(* Logix 5000 project; controller Motion_Axis_AOIs_AMCI_RSLogix_V31 vendor 1 type 14 code 108 rev 31.11; software revision 31.02; part 2 of 7 *)
(* tags used below, declared in another part *)
   Initialize_timer : TIMER;
(* AMCI_MA_Reset_Driver_Fault, continued *)

ROUTINE Logic   (* ladder *)
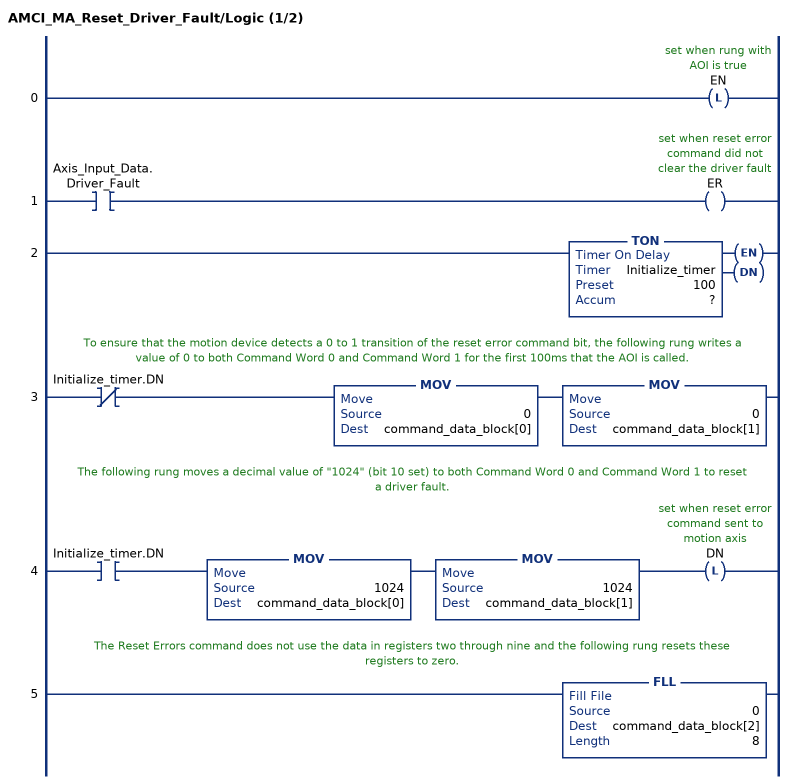
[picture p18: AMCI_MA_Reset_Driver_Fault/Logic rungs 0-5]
   0: OTL(EN);
   1: XIC(Axis_Input_Data.Driver_Fault)OTE(ER);
   2: TON(Initialize_timer,?,?);
   // To ensure that the motion device detects a 0 to 1 transition of the reset error command bit, the following rung writes a value of 0 to both Command Word 0 and Command Word 1 for the first 100ms that the AOI is called.
   3: XIO(Initialize_timer.DN)MOV(0,command_data_block[0])MOV(0,command_data_block[1]);
   // The following rung moves a decimal value of "1024" (bit 10 set) to both Command Word 0 and Command Word 1 to reset a driver fault.
   4: XIC(Initialize_timer.DN)MOV(1024,command_data_block[0])MOV(1024,command_data_block[1])OTL(DN);
   // The Reset Errors command does not use the data in registers two through nine and the following rung resets these registers to zero.
   5: FLL(0,command_data_block[2],8);
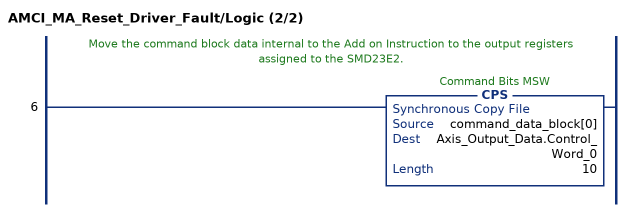
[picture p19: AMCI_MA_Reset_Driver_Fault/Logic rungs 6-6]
   // Move the command block data internal to the Add on Instruction to the output registers assigned to the SMD23E2.
   6: CPS(command_data_block[0],Axis_Output_Data.Control_Word_0,10);
END_ROUTINE
END_ADD_ON_INSTRUCTION

ADD_ON_INSTRUCTION AMCI_MA_Run_Blend_Move   (* revision 1.0, vendor AMCI, ExecuteEnableInFalse *)
// Run Blend Moves for SD and SMD devices.  Will not work with SV integrated servo devices.
// Help:
// MOTION AXIS RUN BLEND MOVE
// This AOI will only work with the SD and SMD motion devices.  The SV motion devices do not support Assembled Moves.
// AXIS INPUT DATA:  Input data from AMCI motion device.   Uses the AMCI_Motion_Axis_Input_Data User Defined Data Type.
// AXIS OUTPUT DATA; Output data from the AOI to the AMCI motion device.   Uses the AMCI_Motion_Axis_Output_Data User Defined Data Type.
// DIRECTION: 0 = CW motion 1 = CCW motion
// EN (Enable) Set when rung is true, Reset when rung is false
// DN (Done) Set when command is sent to the motion device.  Reset when the rung is false.
// ER (Error) Set when a command or input error failed to clear.  Reset when the rung is false.
// IP (In Process) Set when motion is occurring.   Reset when motion stops or the rung goes false.
VAR_IN_OUT
   Axis_Input_Data : AMCI_Motion_Axis_Input_Data; {required}
   Axis_Output_Data : AMCI_Motion_Axis_Output_Data; {required}
END_VAR
VAR_INPUT
   Type_0_for_standard_1_for_indexed : BOOL;
   Direction_0_for_CW_1_for_CCW : BOOL; {required}
END_VAR
VAR_OUTPUT
   EN : BOOL; {access Read Only, visible}
   DN : BOOL; {access Read Only, visible}
   ER : BOOL; {access Read Only, visible}
   IP : BOOL; {access Read Only, visible}
END_VAR
VAR
   command_data_block : INT[10];
        [1]   // Command Bits LSW
        [2]   // Upper Target Position
        [5]   // Lower Programmed Speed
        [0]   // Command Bits MSW
        [4]   // Upper Programmed Speed
        [3]   // Lower Target Position
END_VAR

ROUTINE EnableInFalse   (* ladder *)
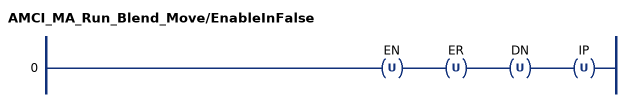
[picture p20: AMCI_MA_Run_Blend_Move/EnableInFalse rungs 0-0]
   0: OTU(EN)OTU(ER)OTU(DN)OTU(IP);
END_ROUTINE

ROUTINE Logic   (* ladder *)
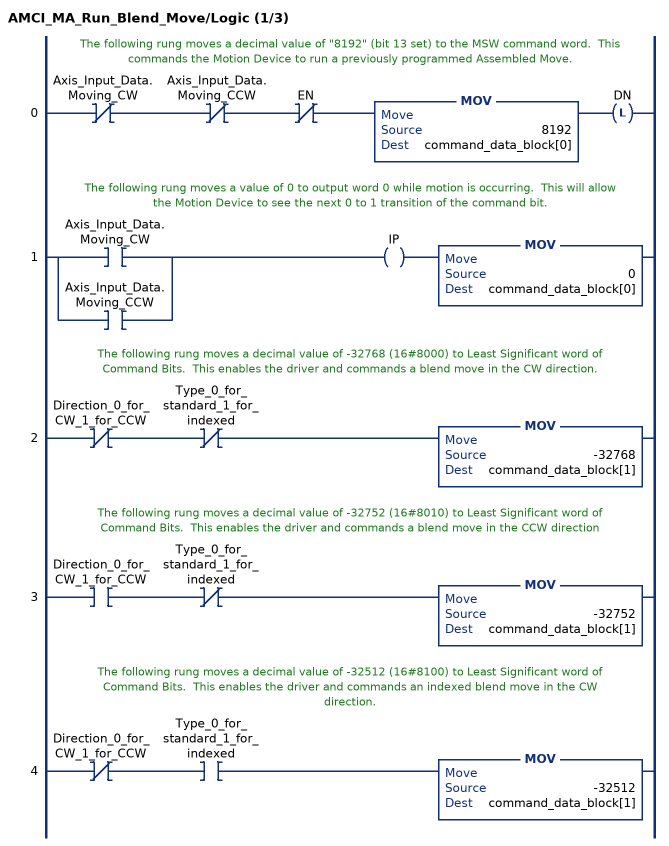
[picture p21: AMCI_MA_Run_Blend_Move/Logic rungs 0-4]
   // The following rung moves a decimal value of "8192" (bit 13 set) to the MSW command word.  This commands the Motion Device to run a previously programmed Assembled Move.
   0: XIO(Axis_Input_Data.Moving_CW)XIO(Axis_Input_Data.Moving_CCW)XIO(EN)MOV(8192,command_data_block[0])OTL(DN);
   // The following rung moves a value of 0 to output word 0 while motion is occurring.  This will allow the Motion Device to see the next 0 to 1 transition of the command bit.
   1: [XIC(Axis_Input_Data.Moving_CW) ,XIC(Axis_Input_Data.Moving_CCW) ]OTE(IP)MOV(0,command_data_block[0]);
   // The following rung moves a decimal value of -32768 (16#8000) to Least Significant word of Command Bits.  This enables the driver and commands a blend move in the CW direction.
   2: XIO(Direction_0_for_CW_1_for_CCW)XIO(Type_0_for_standard_1_for_indexed)MOV(-32768,command_data_block[1]);
   // The following rung moves a decimal value of -32752 (16#8010) to Least Significant word of Command Bits.  This enables the driver and commands a blend move in the CCW direction
   3: XIC(Direction_0_for_CW_1_for_CCW)XIO(Type_0_for_standard_1_for_indexed)MOV(-32752,command_data_block[1]);
   // The following rung moves a decimal value of -32512 (16#8100) to Least Significant word of Command Bits.  This enables the driver and commands an indexed blend move in the CW direction.
   4: XIO(Direction_0_for_CW_1_for_CCW)XIC(Type_0_for_standard_1_for_indexed)MOV(-32512,command_data_block[1]);
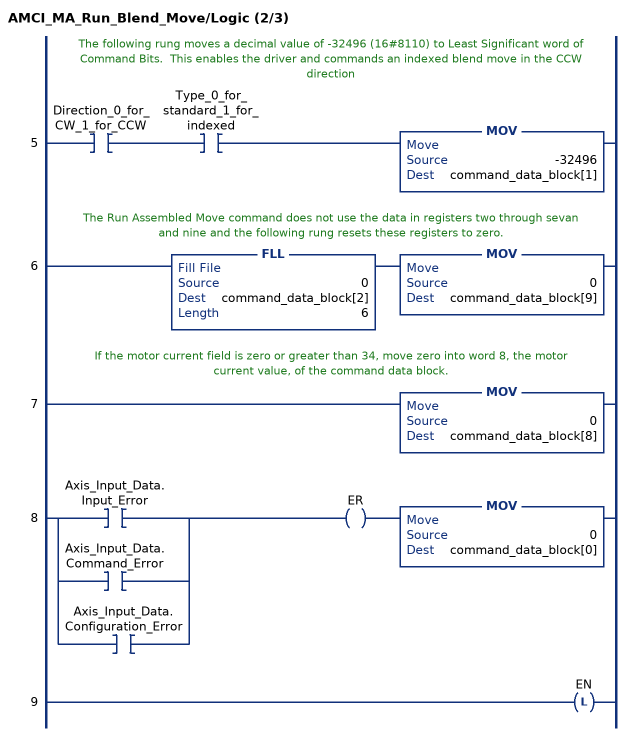
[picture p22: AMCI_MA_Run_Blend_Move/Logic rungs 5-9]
   // The following rung moves a decimal value of -32496 (16#8110) to Least Significant word of Command Bits.  This enables the driver and commands an indexed blend move in the CCW direction
   5: XIC(Direction_0_for_CW_1_for_CCW)XIC(Type_0_for_standard_1_for_indexed)MOV(-32496,command_data_block[1]);
   // The Run Assembled Move command does not use the data in registers two through sevan and nine and the following rung resets these registers to zero.
   6: FLL(0,command_data_block[2],6)MOV(0,command_data_block[9]);
   // If the motor current field is zero or greater than 34, move zero into word 8, the motor current value, of the command data block.
   7: MOV(0,command_data_block[8]);
   8: [XIC(Axis_Input_Data.Input_Error) ,XIC(Axis_Input_Data.Command_Error) ,XIC(Axis_Input_Data.Configuration_Error) ]OTE(ER)MOV(0,command_data_block[0]);
   9: OTL(EN);
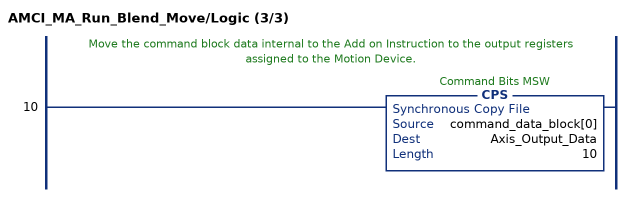
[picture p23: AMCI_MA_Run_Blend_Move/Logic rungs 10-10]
   // Move the command block data internal to the Add on Instruction to the output registers assigned to the Motion Device.
   10: CPS(command_data_block[0],Axis_Output_Data,10);
END_ROUTINE
END_ADD_ON_INSTRUCTION

ADD_ON_INSTRUCTION AMCI_MA_Run_Dwell_Move   (* revision 1.0, vendor AMCI, ExecuteEnableInFalse *)
// Run Dwell Moves for SD and SMD devices.  Will not work with SV integrated servo devices.
// Help:
// MOTION AXIS RUN DWELL MOVE
// This AOI will only work with the SD and SMD motion devices.  The SV motion devices do not support Assembled Moves.
// AXIS INPUT DATA:  Input data from AMCI motion device.   Uses the AMCI_Motion_Axis_Input_Data User Defined Data Type.
// AXIS OUTPUT DATA; Output data from the AOI to the AMCI motion device.   Uses the AMCI_Motion_Axis_Output_Data User Defined Data Type.
// DWELL TIME:Time in milliseconds between each of the assembled move segments.
// EN (Enable) Set when rung is true, Reset when rung is false
// DN (Done) Set when command is sent to the motion device.  Reset when the rung is false.
// ER (Error) Set when a command or input error failed to clear.  Reset when the rung is false.
// IP (In Process) Set when motion is occurring.   Reset when motion stops or the rung goes false.
VAR_IN_OUT
   Axis_Input_Data : AMCI_Motion_Axis_Input_Data; {required}
   Axis_Output_Data : AMCI_Motion_Axis_Output_Data; {required}
END_VAR
VAR_INPUT
   Type_0_for_standard_1_for_indexed : BOOL;
   Dwell_Time : INT; {required}
END_VAR
VAR_OUTPUT
   EN : BOOL; {visible}
   DN : BOOL; {visible}
   ER : BOOL; {visible}
   IP : BOOL; {visible}
END_VAR
VAR
   command_data_block : INT[10];
        [1]   // Command Bits LSW
        [3]   // Lower Target Position
        [5]   // Lower Programmed Speed
        [0]   // Command Bits MSW
        [2]   // Upper Target Position
        [4]   // Upper Programmed Speed
END_VAR

ROUTINE EnableInFalse   (* ladder *)
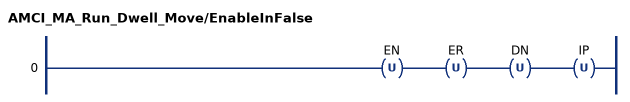
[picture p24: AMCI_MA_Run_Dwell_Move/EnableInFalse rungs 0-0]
   0: OTU(EN)OTU(ER)OTU(DN)OTU(IP);
END_ROUTINE

ROUTINE Logic   (* ladder *)
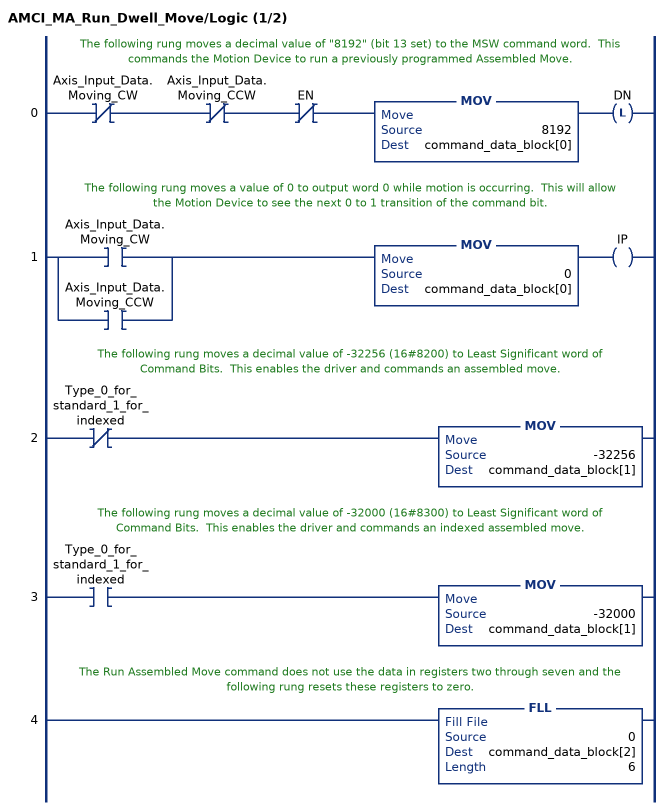
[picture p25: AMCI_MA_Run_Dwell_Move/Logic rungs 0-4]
   // The following rung moves a decimal value of "8192" (bit 13 set) to the MSW command word.  This commands the Motion Device to run a previously programmed Assembled Move.
   0: XIO(Axis_Input_Data.Moving_CW)XIO(Axis_Input_Data.Moving_CCW)XIO(EN)MOV(8192,command_data_block[0])OTL(DN);
   // The following rung moves a value of 0 to output word 0 while motion is occurring.  This will allow the Motion Device to see the next 0 to 1 transition of the command bit.
   1: [XIC(Axis_Input_Data.Moving_CW) ,XIC(Axis_Input_Data.Moving_CCW) ]MOV(0,command_data_block[0])OTE(IP);
   // The following rung moves a decimal value of -32256 (16#8200) to Least Significant word of Command Bits.  This enables the driver and commands an assembled move.
   2: XIO(Type_0_for_standard_1_for_indexed)MOV(-32256,command_data_block[1]);
   // The following rung moves a decimal value of -32000 (16#8300) to Least Significant word of Command Bits.  This enables the driver and commands an indexed assembled move.
   3: XIC(Type_0_for_standard_1_for_indexed)MOV(-32000,command_data_block[1]);
   // The Run Assembled Move command does not use the data in registers two through seven and the following rung resets these registers to zero.
   4: FLL(0,command_data_block[2],6);
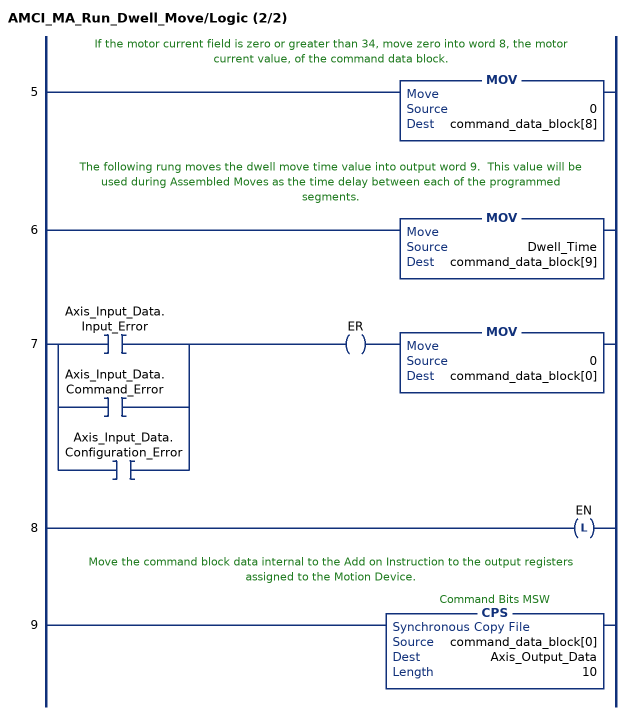
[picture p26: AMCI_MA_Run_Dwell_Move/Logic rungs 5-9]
   // If the motor current field is zero or greater than 34, move zero into word 8, the motor current value, of the command data block.
   5: MOV(0,command_data_block[8]);
   // The following rung moves the dwell move time value into output word 9.  This value will be used during Assembled Moves as the time delay between each of the programmed segments.
   6: MOV(Dwell_Time,command_data_block[9]);
   7: [XIC(Axis_Input_Data.Input_Error) ,XIC(Axis_Input_Data.Command_Error) ,XIC(Axis_Input_Data.Configuration_Error) ]OTE(ER)MOV(0,command_data_block[0]);
   8: OTL(EN);
   // Move the command block data internal to the Add on Instruction to the output registers assigned to the Motion Device.
   9: CPS(command_data_block[0],Axis_Output_Data,10);
END_ROUTINE
END_ADD_ON_INSTRUCTION

ADD_ON_INSTRUCTION AMCI_MA_SD_SMD_Circular_Follower   (* revision 5.0, vendor AMCI, ExecuteEnableInFalse *)
// Circular Axis Follower for SD and SMD devices.  Will not work with SV integrated servo devices.
// Revision note:
// and the jog CW has smoother motion.)
// Help:
// MOTION AXIS SD & SMD CIRCULAR FOLLOWER
// These AOIs will only work with the SD and SMD motion devices.  The SV motion devices have their own follower AOIs.
// AXIS INPUT DATA:  Input data from AMCI motion device.   Uses the AMCI_Motion_Axis_Input_Data User Defined Data Type.
// AXIS OUTPUT DATA; Output data from the AOI to the AMCI motion device.   Uses the AMCI_Motion_Axis_Output_Data User Defined Data Type.
// FOLLOWER POSITION: REAL DATA TYPE position directly from the motion axis.
// FOLLOWER VELOCITY: REAL DATA TYPE velocity directly from the motion axis.
// ACCELERATION & DECELERATION: An actual value or an INT DATA TYPE.  Larger acceleration and
//                                                             deceleration values will cause the motion device to more quickly react
//                                                              changes in the source position and velocity values.
// PROPORTIONAL COEFFICIENT:  A value of 1 or 2 is recommended
// CONVERSION CONSTANT: Converts revolutions and revolutions / sec  from the motion axis to the step and
//                                               steps / sec used by the motion axis.
// POSITION UNWIND: Must be set to the Unwind Value of the motion axis and defines the point at which the
//                                    position data will transition from its maximum to its minimum value.    The Position
//                                    Unwind Value MUST BE IN THE RANGE OF 21 TO 65535.
// EN (Enable) Set when rung is true, Reset when rung is false
// DN (Done) Set when command is sent to the motion device.  Reset when the rung is false.
// ER (Error) Set when a command or input error failed to clear.  Reset when the rung is false.
// IP (In Process) Set when follower command is active, even if motion is not occurring.   Reset when the rung
//                         goes false.
VAR_IN_OUT
   Axis_Input_Data : AMCI_Motion_Axis_Input_Data; {required}
   Axis_Output_Data : AMCI_Motion_Axis_Output_Data; {required}
END_VAR
VAR_INPUT
   _0_for_Normal_1_for_Continuous : BOOL;
   Follower_Position : REAL; {required}
   Follower_Velocity : REAL; {required}
   Acceleration : INT; {required}
   Deceleration : INT; {required}
   Proportional_Coefficient : INT; {required}
   Conversion_Constant : REAL; {required}
   Position_Unwind : INT; {required}
END_VAR
VAR_OUTPUT
   EN : BOOL; {visible}
   DN : BOOL; {access Read Only, visible}
   ER : BOOL; {visible}
   IP : BOOL; {access Read Only, visible}
END_VAR
VAR
   command_data_block : INT[10];
        [1]   // Command Bits LSW
        [3]   // Lower Target Position
        [5]   // Lower Programmed Speed
        [0]   // Command Bits MSW
        [2]   // Upper Target Position
        [4]   // Upper Programmed Speed
   axis_follower_position : DINT;
   axis_follower_velocity : DINT;
END_VAR

ROUTINE EnableInFalse   (* ladder *)
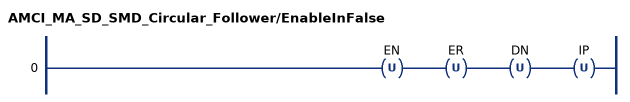
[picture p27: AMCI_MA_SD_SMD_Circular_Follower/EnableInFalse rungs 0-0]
   0: OTU(EN)OTU(ER)OTU(DN)OTU(IP);
END_ROUTINE

ROUTINE Logic   (* ladder *)
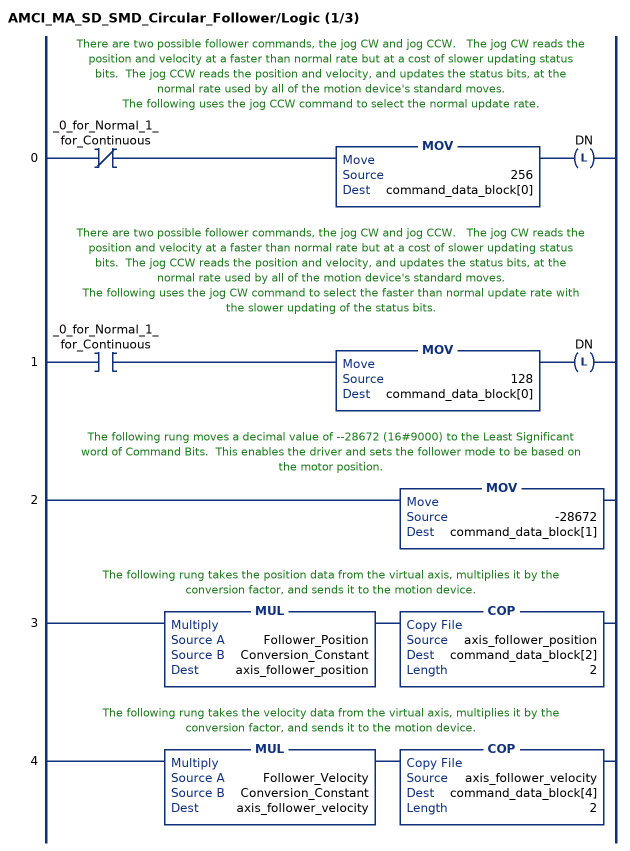
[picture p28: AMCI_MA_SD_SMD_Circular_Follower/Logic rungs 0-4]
   // There are two possible follower commands, the jog CW and jog CCW.   The jog CW reads the position and velocity at a faster than normal rate but at a cost of slower updating status bits.  The jog CCW reads the position and velocity, and updates the status bits, at the normal rate used by all of the motion device's standard moves.
   // The following uses the jog CCW command to select the normal update rate.
   0: XIO(_0_for_Normal_1_for_Continuous)MOV(256,command_data_block[0])OTL(DN);
   // There are two possible follower commands, the jog CW and jog CCW.   The jog CW reads the position and velocity at a faster than normal rate but at a cost of slower updating status bits.  The jog CCW reads the position and velocity, and updates the status bits, at the normal rate used by all of the motion device's standard moves.
   // The following uses the jog CW command to select the faster than normal update rate with the slower updating of the status bits.
   1: XIC(_0_for_Normal_1_for_Continuous)MOV(128,command_data_block[0])OTL(DN);
   // The following rung moves a decimal value of --28672 (16#9000) to the Least Significant word of Command Bits.  This enables the driver and sets the follower mode to be based on the motor position.
   2: MOV(-28672,command_data_block[1]);
   // The following rung takes the position data from the virtual axis, multiplies it by the conversion factor, and sends it to the motion device.
   3: MUL(Follower_Position,Conversion_Constant,axis_follower_position)COP(axis_follower_position,command_data_block[2],2);
   // The following rung takes the velocity data from the virtual axis, multiplies it by the conversion factor, and sends it to the motion device.
   4: MUL(Follower_Velocity,Conversion_Constant,axis_follower_velocity)COP(axis_follower_velocity,command_data_block[4],2);
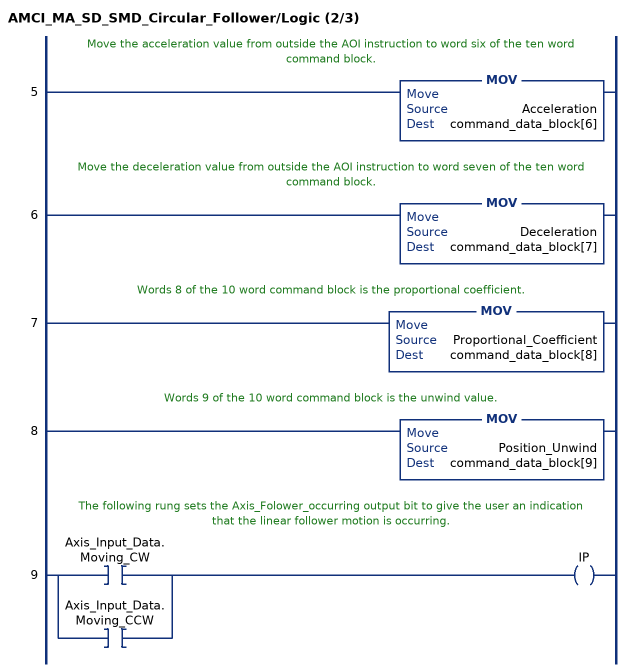
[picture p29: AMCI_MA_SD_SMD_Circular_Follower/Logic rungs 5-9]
   // Move the acceleration value from outside the AOI instruction to word six of the ten word command block.
   5: MOV(Acceleration,command_data_block[6]);
   // Move the deceleration value from outside the AOI instruction to word seven of the ten word command block.
   6: MOV(Deceleration,command_data_block[7]);
   // Words 8 of the 10 word command block is the proportional coefficient.
   7: MOV(Proportional_Coefficient,command_data_block[8]);
   // Words 9 of the 10 word command block is the unwind value.
   8: MOV(Position_Unwind,command_data_block[9]);
   // The following rung sets the Axis_Folower_occurring output bit to give the user an indication that the linear follower motion is occurring.
   9: [XIC(Axis_Input_Data.Moving_CW) ,XIC(Axis_Input_Data.Moving_CCW) ]OTE(IP);
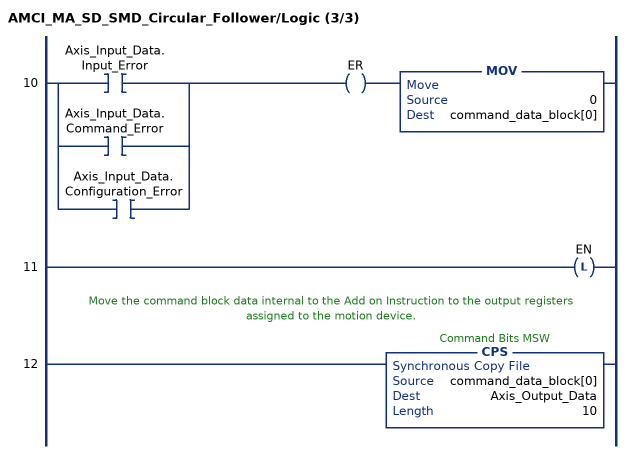
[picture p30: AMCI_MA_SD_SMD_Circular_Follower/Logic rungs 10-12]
   10: [XIC(Axis_Input_Data.Input_Error) ,XIC(Axis_Input_Data.Command_Error) ,XIC(Axis_Input_Data.Configuration_Error) ]OTE(ER)MOV(0,command_data_block[0]);
   11: OTL(EN);
   // Move the command block data internal to the Add on Instruction to the output registers assigned to the motion device.
   12: CPS(command_data_block[0],Axis_Output_Data,10);
END_ROUTINE
END_ADD_ON_INSTRUCTION

ADD_ON_INSTRUCTION AMCI_MA_SD_SMD_Circular_Follower_CIPSYNC   (* revision 1.0, vendor AMCI, ExecuteEnableInFalse *)
// Circular Axis Follower for SD and SMD devices.  Will not work with SV integrated servo devices.
// Revision note:
// 8/8/24.  Added timesync functionality to a previously existing AOI.  Also added logic to preset the motor position to the master axis position when the rung with the AOI becomes true, or if the master axis position changes when motion is not occurring.
// Help:
// MOTION AXIS SD & SMD CIRCULAR FOLLOWER
// These AOIs will only work with the SD and SMD motion devices.  The SV motion devices have their own follower AOIs.
// AXIS INPUT DATA:  Input data from AMCI motion device.   Uses the AMCI_Motion_Axis_Input_Data User Defined Data Type.
// AXIS OUTPUT DATA; Output data from the AOI to the AMCI motion device.   Uses the AMCI_Motion_Axis_Output_Data User Defined Data Type.
// FOLLOWER POSITION: REAL DATA TYPE position directly from the motion axis.
// FOLLOWER VELOCITY: REAL DATA TYPE velocity directly from the motion axis.
// ACCELERATION & DECELERATION: An actual value or an INT DATA TYPE.  Larger acceleration and
//                                                             deceleration values will cause the motion device to more quickly react
//                                                              changes in the source position and velocity values.
// PROPORTIONAL COEFFICIENT:  A value of 1 or 2 is recommended
// CONVERSION CONSTANT: Converts revolutions and revolutions / sec  from the motion axis to the step and
//                                               steps / sec used by the motion axis.
// POSITION UNWIND: Must be set to the Unwind Value of the motion axis and defines the point at which the
//                                    position data will transition from its maximum to its minimum value.    The Position
//                                    Unwind Value MUST BE IN THE RANGE OF 21 TO 65535.
// RPI_TIME: The RPI time used when adding the AMCI Motion device to the network.   8ms is the default.
//                    Used to control how long the preset motor command is sent to the device when the rung with the
//                    AOI transitions from false to true.
// TIMESYNC: The PLC's time value used to more closely synchronize the motion data from the PLC's master
//                     axis with the output of the AMCI motion device.
// EN (Enable) Set when rung is true, Reset when rung is false
// DN (Done) Set when command is sent to the motion device.  Reset when the rung is false.
// ER (Error) Set when a command or input error failed to clear.  Reset when the rung is false.
// IP (In Process) Set when follower command is active, even if motion is not occurring.   Reset when the rung
//                         goes false.
VAR_IN_OUT
   Axis_Input_Data : AMCI_Motion_Axis_Input_Data; {required}
   Axis_Output_Data : AMCI_Motion_Axis_Output_Data; {required}
END_VAR
VAR_INPUT
   Current_System_Time : DINT; {required}
   _0_for_Normal_1_for_Continuous : BOOL;
   Master_Axis_Position : REAL; {required}
   Master_Axis_Velocity : REAL; {required}
   Acceleration : INT; {required}
   Deceleration : INT; {required}
   Proportional_Coefficient : INT; {required}
   Conversion_Constant : REAL; {required}
   Position_Unwind : INT; {required}
   RPI_Time_in_ms : DINT; {required}
END_VAR
VAR_OUTPUT
   EN : BOOL; {visible}
   DN : BOOL; {access Read Only, visible}
   ER : BOOL; {visible}
   IP : BOOL; {access Read Only, visible}
END_VAR
VAR
   command_data_block : INT[10];
        [1]   // Command Bits LSW
        [3]   // Lower Target Position
        [5]   // Lower Programmed Speed
        [0]   // Command Bits MSW
        [2]   // Upper Target Position
        [4]   // Upper Programmed Speed
   axis_follower_position : DINT;
   axis_follower_velocity : DINT;
   preset_motor_position_timer_circular : TIMER; {access None}
   position_last_scan_circular_SMD : DINT; {access None}
   position_difference : DINT; {access None}
   preset_one_shot : BOOL; {access None}
END_VAR

ROUTINE EnableInFalse   (* ladder *)
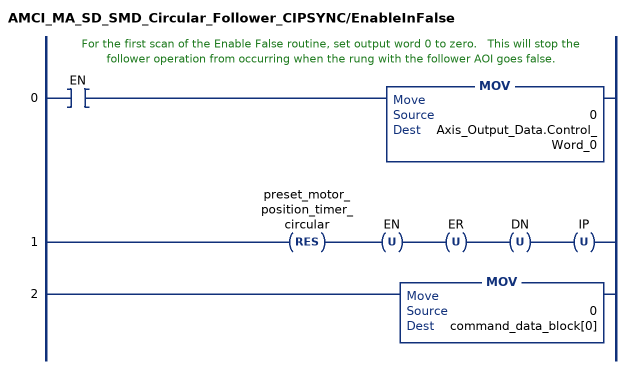
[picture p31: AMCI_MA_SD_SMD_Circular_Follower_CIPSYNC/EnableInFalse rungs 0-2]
   // For the first scan of the Enable False routine, set output word 0 to zero.   This will stop the follower operation from occurring when the rung with the follower AOI goes false.
   0: XIC(EN)MOV(0,Axis_Output_Data.Control_Word_0);
   1: RES(preset_motor_position_timer_circular)OTU(EN)OTU(ER)OTU(DN)OTU(IP);
   2: MOV(0,command_data_block[0]);
END_ROUTINE

ROUTINE Logic   (* ladder *)
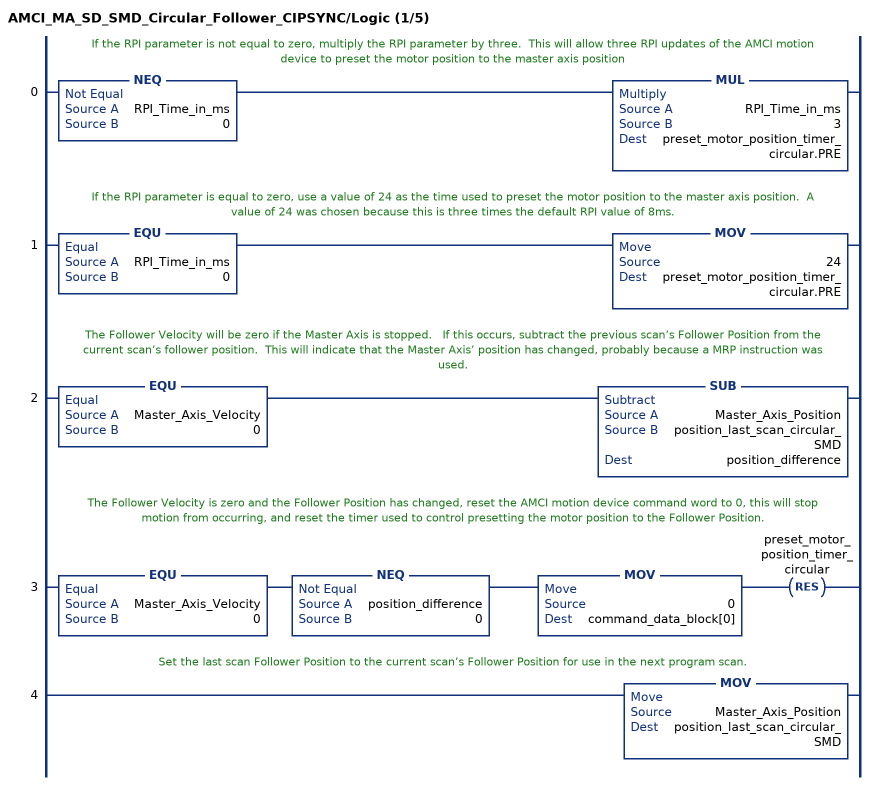
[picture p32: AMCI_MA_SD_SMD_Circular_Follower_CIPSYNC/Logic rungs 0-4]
   // If the RPI parameter is not equal to zero, multiply the RPI parameter by three.  This will allow three RPI updates of the AMCI motion device to preset the motor position to the master axis position
   0: NEQ(RPI_Time_in_ms,0)MUL(RPI_Time_in_ms,3,preset_motor_position_timer_circular.PRE);
   // If the RPI parameter is equal to zero, use a value of 24 as the time used to preset the motor position to the master axis position.  A value of 24 was chosen because this is three times the default RPI value of 8ms.
   1: EQU(RPI_Time_in_ms,0)MOV(24,preset_motor_position_timer_circular.PRE);
   // The Follower Velocity will be zero if the Master Axis is stopped.   If this occurs, subtract the previous scan’s Follower Position from the current scan’s follower position.  This will indicate that the Master Axis’ position has changed, probably because a MRP instruction was used.
   2: EQU(Master_Axis_Velocity,0)SUB(Master_Axis_Position,position_last_scan_circular_SMD,position_difference);
   // The Follower Velocity is zero and the Follower Position has changed, reset the AMCI motion device command word to 0, this will stop motion from occurring, and reset the timer used to control presetting the motor position to the Follower Position.
   3: EQU(Master_Axis_Velocity,0)NEQ(position_difference,0)MOV(0,command_data_block[0])RES(preset_motor_position_timer_circular);
   // Set the last scan Follower Position to the current scan’s Follower Position for use in the next program scan.
   4: MOV(Master_Axis_Position,position_last_scan_circular_SMD);
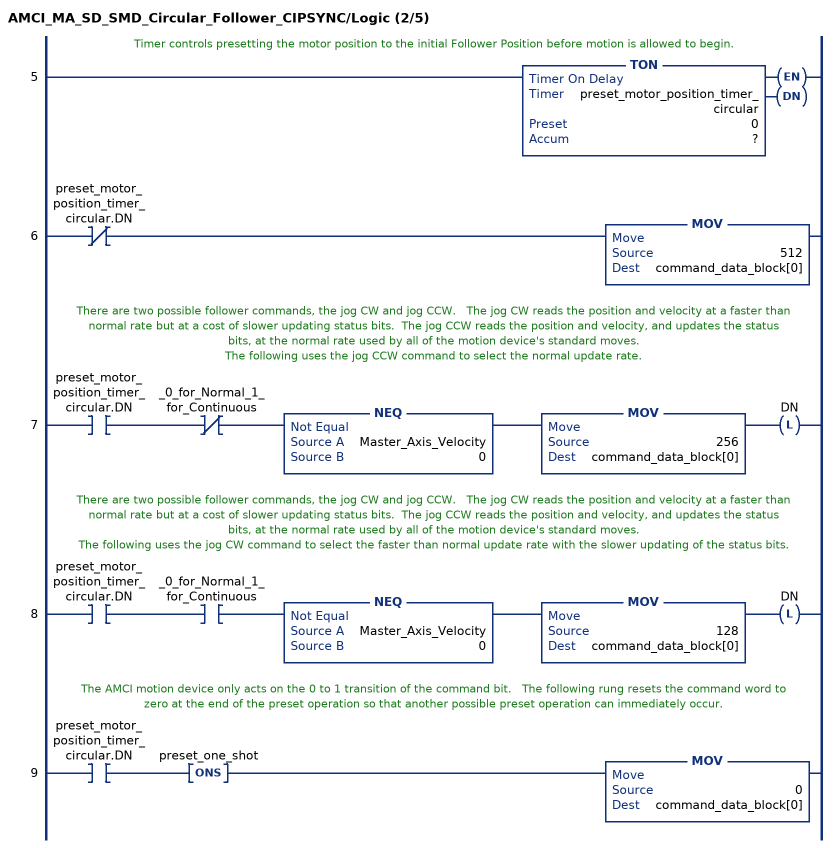
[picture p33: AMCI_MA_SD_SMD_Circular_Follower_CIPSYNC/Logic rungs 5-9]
   // Timer controls presetting the motor position to the initial Follower Position before motion is allowed to begin.
   5: TON(preset_motor_position_timer_circular,?,?);
   6: XIO(preset_motor_position_timer_circular.DN)MOV(512,command_data_block[0]);
   // There are two possible follower commands, the jog CW and jog CCW.   The jog CW reads the position and velocity at a faster than normal rate but at a cost of slower updating status bits.  The jog CCW reads the position and velocity, and updates the status bits, at the normal rate used by all of the motion device's standard moves.
   // The following uses the jog CCW command to select the normal update rate.
   7: XIC(preset_motor_position_timer_circular.DN)XIO(_0_for_Normal_1_for_Continuous)NEQ(Master_Axis_Velocity,0)MOV(256,command_data_block[0])OTL(DN);
   // There are two possible follower commands, the jog CW and jog CCW.   The jog CW reads the position and velocity at a faster than normal rate but at a cost of slower updating status bits.  The jog CCW reads the position and velocity, and updates the status bits, at the normal rate used by all of the motion device's standard moves.
   // The following uses the jog CW command to select the faster than normal update rate with the slower updating of the status bits.
   8: XIC(preset_motor_position_timer_circular.DN)XIC(_0_for_Normal_1_for_Continuous)NEQ(Master_Axis_Velocity,0)MOV(128,command_data_block[0])OTL(DN);
   // The AMCI motion device only acts on the 0 to 1 transition of the command bit.   The following rung resets the command word to zero at the end of the preset operation so that another possible preset operation can immediately occur.
   9: XIC(preset_motor_position_timer_circular.DN)ONS(preset_one_shot)MOV(0,command_data_block[0]);
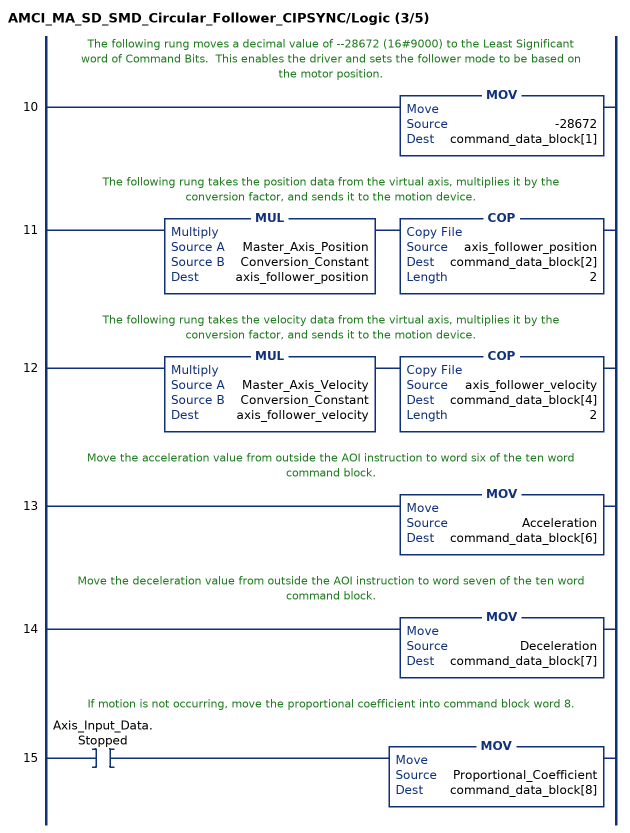
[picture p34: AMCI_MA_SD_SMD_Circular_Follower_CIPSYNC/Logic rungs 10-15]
   // The following rung moves a decimal value of --28672 (16#9000) to the Least Significant word of Command Bits.  This enables the driver and sets the follower mode to be based on the motor position.
   10: MOV(-28672,command_data_block[1]);
   // The following rung takes the position data from the virtual axis, multiplies it by the conversion factor, and sends it to the motion device.
   11: MUL(Master_Axis_Position,Conversion_Constant,axis_follower_position)COP(axis_follower_position,command_data_block[2],2);
   // The following rung takes the velocity data from the virtual axis, multiplies it by the conversion factor, and sends it to the motion device.
   12: MUL(Master_Axis_Velocity,Conversion_Constant,axis_follower_velocity)COP(axis_follower_velocity,command_data_block[4],2);
   // Move the acceleration value from outside the AOI instruction to word six of the ten word command block.
   13: MOV(Acceleration,command_data_block[6]);
   // Move the deceleration value from outside the AOI instruction to word seven of the ten word command block.
   14: MOV(Deceleration,command_data_block[7]);
   // If motion is not occurring, move the proportional coefficient into command block word 8.
   15: XIC(Axis_Input_Data.Stopped)MOV(Proportional_Coefficient,command_data_block[8]);
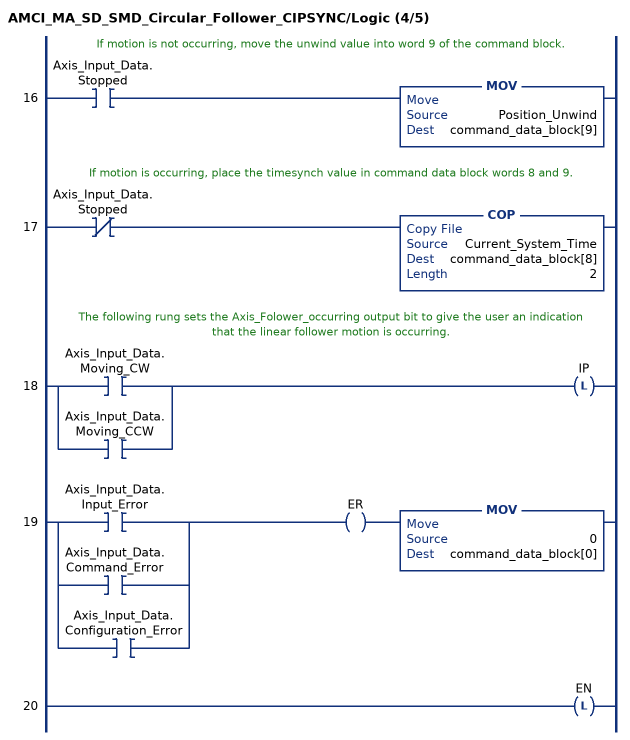
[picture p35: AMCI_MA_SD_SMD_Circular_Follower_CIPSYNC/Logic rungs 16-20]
   // If motion is not occurring, move the unwind value into word 9 of the command block.
   16: XIC(Axis_Input_Data.Stopped)MOV(Position_Unwind,command_data_block[9]);
   // If motion is occurring, place the timesynch value in command data block words 8 and 9.
   17: XIO(Axis_Input_Data.Stopped)COP(Current_System_Time,command_data_block[8],2);
   // The following rung sets the Axis_Folower_occurring output bit to give the user an indication that the linear follower motion is occurring.
   18: [XIC(Axis_Input_Data.Moving_CW) ,XIC(Axis_Input_Data.Moving_CCW) ]OTL(IP);
   19: [XIC(Axis_Input_Data.Input_Error) ,XIC(Axis_Input_Data.Command_Error) ,XIC(Axis_Input_Data.Configuration_Error) ]OTE(ER)MOV(0,command_data_block[0]);
   20: OTL(EN);
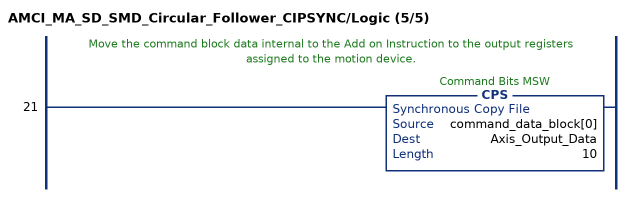
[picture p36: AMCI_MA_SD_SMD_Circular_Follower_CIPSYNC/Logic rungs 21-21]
   // Move the command block data internal to the Add on Instruction to the output registers assigned to the motion device.
   21: CPS(command_data_block[0],Axis_Output_Data,10);
END_ROUTINE
END_ADD_ON_INSTRUCTION
